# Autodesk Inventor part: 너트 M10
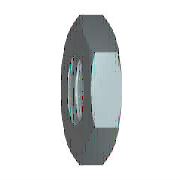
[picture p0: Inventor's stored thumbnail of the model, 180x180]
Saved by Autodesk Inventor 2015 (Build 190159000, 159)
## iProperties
IsCustomPart: 1
Created: 2012-02
Part Number: 너트 M10
Material: 강철, 연강
Description: 6각 가는 너트 - 이중 모따기
Document SubType Name: Modeling
Standard: JIS B 1181
Designer: mduedu
Standards Organization: JIS
Language: ko-KR
Size Designation: A/B M10
Categories: <MemberInstance><Categories><Category DisplayName="조임쇠" InternalName="e4da775c-781d-43d5-af7c-5136215cf5a6" Mnemonic="FSTN"><Category DisplayName="너트" InternalN
Density: 1 g/cm^3
Appearance: 주황색
Author: mduedu
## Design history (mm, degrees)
sketch "스케치1"
  geometry: L1 (-9.238, 0)-(-4.619, 8); L2 (-4.619, 8)-(4.619, 8); L3 (4.619, 8)-(9.238, 0); L4 (9.238, 0)-(4.619, -8); L5 (4.619, -8)-(-4.619, -8); L6 (-4.619, -8)-(-9.238, 0); 2 further points
  constraints: 12 end point, 1 coincident, 1 horizontal, 11 other
  dimensions: "d0" = 18.47521 distance of L3.end L1.start (= 1.1547 x SW)
extrude "본체" new body sketch "스케치1" distance "d1" = 5 (= KOH); taper "d2" = 0 deg
sketch "스케치2"
  geometry: L1 (0, 4.619)-(0, 9.238) reference; L2 (0, 9.238)-(5, 9.238) reference; L3 (5, 4.619)-(5, 9.238) reference; L4 (-1, 0)-(6, 0) reference; L5 (0.715, 9.238)-(0, 8); L6 (4.285, 9.238)-(5, 8)
  constraints: 4 end point, 4 point on line
  dimensions: "d3" = 30 deg angle of L1 L5 (= ANG1); "d4" = 30 deg angle of L3 L6 (= ANG2); "d5" = 16 diameter of L5.end L4 (= SW0); "d6" = 16 diameter of L6.end L4 (= SW01)
revolve "모따기1" sketch "스케치2" stored, may be unused: angle "d7" = 90 deg
sketch "스케치3"
  geometry: A1 r 8 centre (0, 0) between (-4, -6.928) and (4, -6.928) reference; 1 further point
  constraints: 1 coincident
hole "스레드" sketch "스케치3" at (0, 0) diameter "d25" = 8.376; stored, may be unused: countersink angle "d29" = 82 deg, drill point angle "d31" = 118 deg; dims "d26" = 6, "d27" = 4, "d28" = 2, "d30" = 8
workaxis "Work Axis1"
workplane "Work Plane1"
body "Solid1"
chamfer "모따기2" distance "d8" = 0.8119 (= -0.5 x GD1 + 0.5 x NND); stored, may be unused: angle "d9" = 30 deg, second distance "d40" = 0.8119 (= -0.5 x GD1 + 0.5 x NND)
chamfer "모따기3" distance "d10" = 0.8119 (= -0.5 x GD1 + 0.5 x NND); stored, may be unused: angle "d11" = 30 deg, second distance "d41" = 0.8119 (= -0.5 x GD1 + 0.5 x NND)
other parameters: "ANG1" = 30 deg [user parameter; used in 1 equation term], "ANG2" = 30 deg [user parameter; used in 1 equation term], "KOH" = 5 [user parameter; used in 1 equation term], "SW" = 16 [user parameter; used in 4 equation terms], "SW0" = 16 (= SW) [user parameter; used in 1 equation term], "SW01" = 16 (= SW) [user parameter; used in 1 equation term], "GD1" = 8.3762 (computed from THREADDIA, PTC, TOA) [user parameter; used in 4 equation terms], "d13" = 0, "d14" = 0, "d39" = 0, "d42" = 0, "GUL" = 0.8119 (= 0.541266 x PTC) [user parameter], "TPU" = 6.66667 (computed from PTC) [user parameter], "TOA" = 30 deg [user parameter; used in 1 equation term], "PTC" = 1.5 [user parameter; used in 4 equation terms], "E0" = 18.48 (= 1.155 x SW) [user parameter], "GAL" = 0.8119 (= 0.541266 x PTC) [user parameter]
